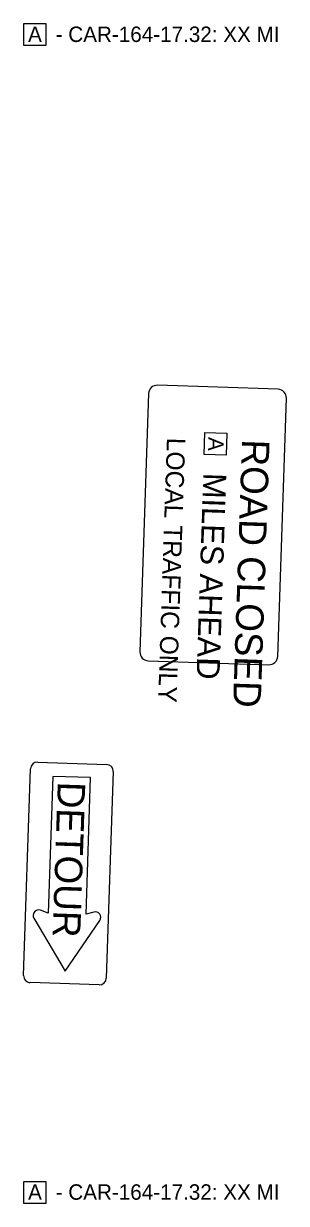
# Model space of a CAD drawing. Extents: x -202 to 1556, y 0 to 676.
# Drawn here: x 297.4 to 345.1, y 461.5 to 675.5 of the extents above; entities that cross this region are included whole.
import ezdxf

# ---------------------------------------------------------------- set-up
doc = ezdxf.new("R2010")
doc.units = 0
for name, color, linetype in [('GM_X_Minor_Lake', 7, 'Continuous'), ('GM_X_Minor_Lake_Text', 7, 'Continuous'), ('GM_X_Minor_River_Text', 7, 'Continuous')]:
    doc.layers.add(name, color=color, linetype=linetype)

msp = doc.modelspace()

# ---------------------------------------------------------------- linework, layer by layer
at = {"layer": 'GM_X_Minor_Lake'}
for p, q in [((302.72, 538.99), (301.89, 514.21)), ((309.59, 538.76), (302.72, 538.99)), ((308.76, 513.98), (309.59, 538.76)), ((301.89, 514.21), (300.52, 514.7)), ((310.16, 514.38), (308.76, 513.98)), ((299.32, 513.25), (304.98, 503.69)), ((304.98, 503.69), (311.26, 512.85))]:
    msp.add_line(p, q, dxfattribs=at)
for points in [[(300, 541.58), (312.49, 541.16)], [(297.45, 502.9), (298.71, 540.37)], [(313.7, 539.87), (312.44, 502.39)], [(311.15, 501.19), (298.66, 501.6)]]:
    msp.add_lwpolyline(points, dxfattribs=at)
for centre, radius, start, end in [((299.95, 540.33), 1.25, 88.0794, 178.0794), ((312.45, 539.91), 1.25, 358.0794, 88.0794), ((300.18, 513.76), 1, 70.2605, 210.5903), ((310.44, 513.42), 1, 325.5686, 105.8983), ((298.7, 502.85), 1.25, 178.0794, 268.0794), ((311.19, 502.43), 1.25, 268.0794, 358.0794)]:
    msp.add_arc(centre, radius, start, end, dxfattribs=at)
at = {"layer": 'GM_X_Minor_Lake_Text'}
for points in [[(343.58, 609.21), (321.72, 609.94)], [(320.1, 608.43), (318.53, 561.58)], [(343.52, 560.74), (345.09, 607.59)], [(320.04, 559.97), (341.9, 559.23)]]:
    msp.add_lwpolyline(points, dxfattribs=at)
for centre, start, end in [((321.66, 608.38), 88.0794, 178.0794), ((343.53, 607.64), 358.0794, 88.0794), ((320.09, 561.53), 178.0794, 268.0794), ((341.95, 560.8), 268.0794, 358.0794)]:
    msp.add_arc(centre, 1.56, start, end, dxfattribs=at)
at = {"layer": 'GM_X_Minor_River_Text'}
for points in [[(297.46, 675.54), (301.46, 675.54), (301.46, 671.54), (297.46, 671.54)], [(334.3, 601.25), (334.17, 597.25), (330.17, 597.38), (330.31, 601.38)], [(297.46, 465.54), (301.46, 465.54), (301.46, 461.54), (297.46, 461.54)]]:
    msp.add_lwpolyline(points, close=True, dxfattribs=at)

# ---------------------------------------------------------------- texts
at = {"layer": 'GM_X_Minor_Lake'}
msp.add_text('DETOUR', height=5, rotation=268.0794, dxfattribs=at).set_placement((303.65, 538.08))
at = {"layer": 'GM_X_Minor_Lake_Text'}
for s, height, p in [('LOCAL TRAFFIC ONLY', 3.3333, (323.44, 600.46)), ('ROAD CLOSED', 5, (337.05, 600.18)), ('MILES AHEAD', 4.1667, (330.04, 594.08))]:
    msp.add_text(s, height=height, rotation=268.0794, dxfattribs=at).set_placement(p)
at = {"layer": 'GM_X_Minor_River_Text'}
for s, p in [('A', (298.26, 672.2)), ('- CAR-164-17.32: XX MI', (303.26, 672.2)), ('A', (298.26, 462.2)), ('- CAR-164-17.32: XX MI', (303.26, 462.2))]:
    msp.add_text(s, height=2.8, dxfattribs=at).set_placement(p)
msp.add_text('A', height=2.8, rotation=268.0794, dxfattribs=at).set_placement((330.94, 600.56))

doc.saveas('drawing.dxf')
